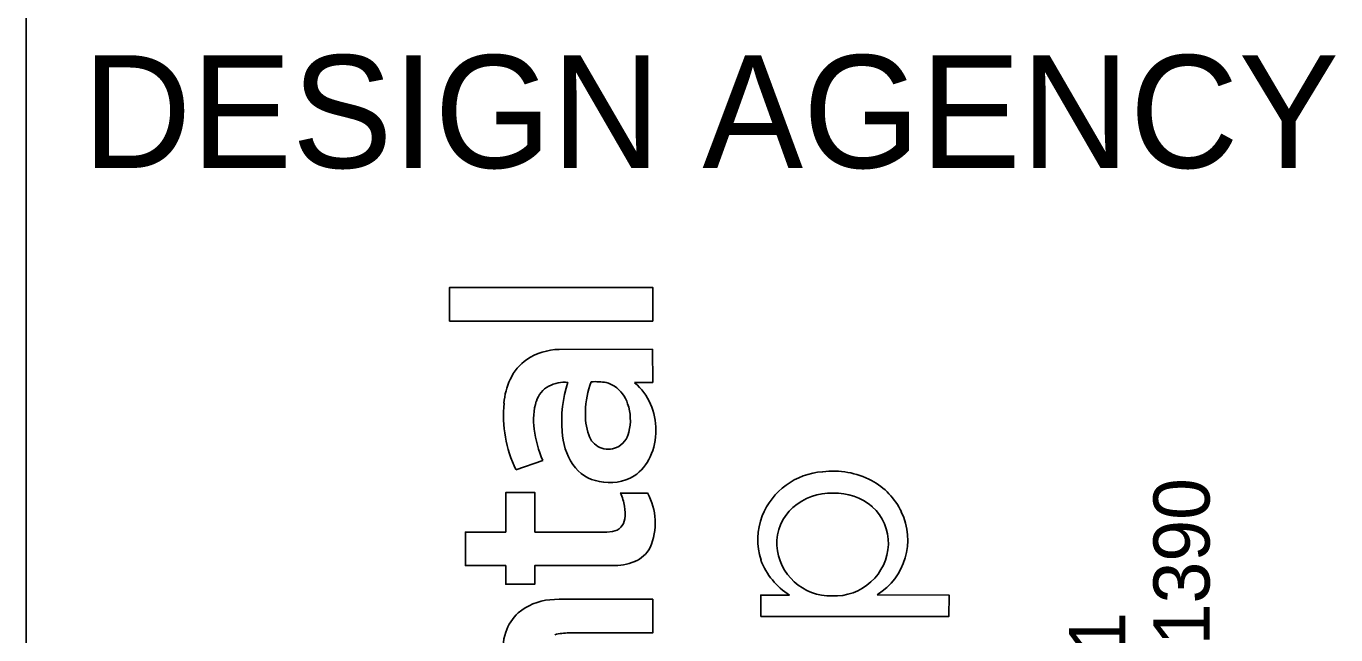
# Model space of a CAD drawing. Extents: x -0.3 to 34, y 0 to 22.
# Drawn here: x 32 to 33.162, y 3.936 to 4.476 of the extents above; entities that cross this region are included whole.
import ezdxf

# ---------------------------------------------------------------- set-up
doc = ezdxf.new("R2010")
doc.units = 0
doc.layers.add('RD_X_Misc_Items', color=7, linetype='Continuous')
doc.layers.add('SV_X_Control_Cells_Found', color=7, linetype='Continuous')

msp = doc.modelspace()

# ---------------------------------------------------------------- linework, layer by layer
at = {"layer": 'RD_X_Misc_Items'}
for p, q in [((32.3756, 4.2141), (32.3756, 4.244)), ((32.3756, 4.244), (32.5557, 4.244)), ((32.5557, 4.244), (32.5557, 4.2141)), ((32.5557, 4.2141), (32.3756, 4.2141)), ((32.4727, 4.189), (32.5555, 4.1892)), ((32.5555, 4.1892), (32.5557, 4.1596)), ((32.5557, 4.1596), (32.5397, 4.1596)), ((32.4582, 4.0904), (32.4343, 4.0823)), ((32.4254, 4.027), (32.4255, 4.0621)), ((32.4255, 4.0621), (32.4511, 4.0621)), ((32.4511, 4.0621), (32.4512, 4.027)), ((32.527, 4.0616), (32.5511, 4.0616)), ((32.3896, 3.9972), (32.3896, 4.027)), ((32.3896, 4.027), (32.4254, 4.027)), ((32.4512, 4.027), (32.515, 4.027)), ((32.515, 4.027), (32.52, 4.0275)), ((32.4254, 3.9972), (32.3896, 3.9972)), ((32.4254, 3.9807), (32.4254, 3.9972)), ((32.5197, 3.9972), (32.4511, 3.9972)), ((32.4511, 3.9972), (32.4511, 3.9807)), ((32.4511, 3.9807), (32.4254, 3.9807)), ((32.4644, 3.9669), (32.4729, 3.9673)), ((32.4729, 3.9673), (32.5557, 3.9673)), ((32.5557, 3.9673), (32.5557, 3.9375)), ((32.6515, 3.9521), (32.6515, 3.9711)), ((32.6515, 3.9711), (32.6771, 3.9711)), ((32.7549, 3.9713), (32.8186, 3.9711)), ((32.8186, 3.9711), (32.8184, 3.9521)), ((32.8184, 3.9521), (32.6515, 3.9521)), ((32.5557, 3.9375), (32.4814, 3.9375))]:
    msp.add_line(p, q, dxfattribs=at)
msp.add_lwpolyline([(32.3756, 4.2141), (32.3756, 4.244), (32.5557, 4.244), (32.5557, 4.2141)], close=True, dxfattribs=at)
for points in [[(32.4727, 4.189), (32.5555, 4.1892), (32.5557, 4.1596)], [(32.5557, 4.1596), (32.5397, 4.1596)], [(32.4582, 4.0904), (32.4343, 4.0823)], [(32.5197, 3.9972), (32.4511, 3.9972), (32.4511, 3.9807), (32.4254, 3.9807), (32.4254, 3.9972), (32.3896, 3.9972), (32.3896, 4.027), (32.4254, 4.027), (32.4255, 4.0621), (32.4511, 4.0621), (32.4512, 4.027), (32.515, 4.027), (32.52, 4.0275)], [(32.527, 4.0616), (32.5511, 4.0616)], [(32.4644, 3.9669), (32.4729, 3.9673), (32.5557, 3.9673), (32.5557, 3.9375), (32.4814, 3.9375)], [(32.7549, 3.9713), (32.8186, 3.9711), (32.8184, 3.9521), (32.6515, 3.9521)], [(32.6515, 3.9521), (32.6515, 3.9711), (32.6771, 3.9711)]]:
    msp.add_lwpolyline(points, dxfattribs=at)
for centre, radius, start, end in [((32.4745, 4.1326), 0.0565, 91.8942, 122.6317), ((32.4745, 4.1326), 0.0565, 91.8942, 122.6317), ((32.4685, 4.1447), 0.043, 124.537, 155.6594), ((32.4685, 4.1447), 0.043, 124.537, 155.6594), ((32.4882, 4.1361), 0.0646, 155.9764, 175.3149), ((32.4882, 4.1361), 0.0646, 155.9764, 175.3149), ((32.4779, 4.1278), 0.0321, 85.3802, 116.6222), ((32.4779, 4.1278), 0.0321, 85.3802, 116.6222), ((32.5879, 4.1251), 0.1129, 162.0821, 184.5285), ((32.5879, 4.1251), 0.1129, 162.0821, 184.5285), ((32.5801, 4.1313), 0.0841, 159.8366, 178.0362), ((32.5801, 4.1313), 0.0841, 159.8366, 178.0362), ((32.5051, 4.1074), 0.053, 79.6696, 94.2322), ((32.5051, 4.1074), 0.053, 79.6696, 94.2322), ((32.5089, 4.1364), 0.0238, 56.8913, 76.2149), ((32.5089, 4.1364), 0.0238, 56.8913, 76.2149), ((32.5055, 4.1191), 0.0529, 358.0746, 49.762), ((32.5055, 4.1191), 0.0529, 358.0746, 49.762), ((32.4753, 4.1356), 0.024, 119.4252, 161.6629), ((32.4753, 4.1356), 0.024, 119.4252, 161.6629), ((32.5052, 4.1318), 0.0297, 17.5984, 55.7282), ((32.5052, 4.1318), 0.0297, 17.5984, 55.7282), ((32.5364, 4.1308), 0.113, 174.6101, 205.3899), ((32.5364, 4.1308), 0.113, 174.6101, 205.3899), ((32.5076, 4.1265), 0.0576, 163.1369, 188.1675), ((32.5076, 4.1265), 0.0576, 163.1369, 188.1675), ((32.4916, 4.1264), 0.0443, 345.9408, 18.9919), ((32.4916, 4.1264), 0.0443, 345.9408, 18.9919), ((32.5466, 4.1303), 0.0506, 175.5903, 199.8857), ((32.5466, 4.1303), 0.0506, 175.5903, 199.8857), ((32.5473, 4.1297), 0.0973, 186.7598, 203.7981), ((32.5473, 4.1297), 0.0973, 186.7598, 203.7981), ((32.5328, 4.1187), 0.0575, 182.5676, 213.7144), ((32.5328, 4.1187), 0.0575, 182.5676, 213.7144), ((32.5164, 4.1189), 0.0184, 198.2844, 293.3081), ((32.5164, 4.1189), 0.0184, 198.2844, 293.3081), ((32.5152, 4.1199), 0.0199, 295.2883, 347.4639), ((32.5152, 4.1199), 0.0199, 295.2883, 347.4639), ((32.5019, 4.1168), 0.0566, 336.016, 0.5951), ((32.5019, 4.1168), 0.0566, 336.016, 0.5951), ((32.5175, 4.1097), 0.0394, 303.4436, 336.18), ((32.5175, 4.1097), 0.0394, 303.4436, 336.18), ((32.5149, 4.1078), 0.0366, 215.0668, 259.8133), ((32.5149, 4.1078), 0.0366, 215.0668, 259.8133), ((32.7108, 4.0182), 0.0624, 93.9866, 158.3119), ((32.7108, 4.0182), 0.0624, 93.9866, 158.3119), ((32.7156, 4.0065), 0.0746, 62.6889, 97.0135), ((32.7156, 4.0065), 0.0746, 62.6889, 97.0135), ((32.5175, 4.1131), 0.0423, 257.5256, 300.882), ((32.5175, 4.1131), 0.0423, 257.5256, 300.882), ((32.7212, 4.0191), 0.0608, 25.0657, 61.9602), ((32.7212, 4.0191), 0.0608, 25.0657, 61.9602), ((32.4863, 4.042), 0.0452, 10.1545, 25.723), ((32.4863, 4.042), 0.0452, 10.1545, 25.723), ((32.503, 4.0351), 0.0549, 336.589, 28.8991), ((32.503, 4.0351), 0.0549, 336.589, 28.8991), ((32.7138, 4.0102), 0.0513, 87.8965, 131.1812), ((32.7138, 4.0102), 0.0513, 87.8965, 131.1812), ((32.7175, 4.0102), 0.0513, 49.9089, 92.0363), ((32.7175, 4.0102), 0.0513, 49.9089, 92.0363), ((32.4957, 4.0436), 0.0356, 351.914, 10.2059), ((32.4957, 4.0436), 0.0356, 351.914, 10.2059), ((32.7092, 4.0167), 0.0434, 132.3289, 182.0949), ((32.7092, 4.0167), 0.0434, 132.3289, 182.0949), ((32.7215, 4.0173), 0.0433, 358.0487, 47.9447), ((32.7215, 4.0173), 0.0433, 358.0487, 47.9447), ((32.7245, 4.02), 0.0574, 301.9776, 25.6418), ((32.7245, 4.02), 0.0574, 301.9776, 25.6418), ((32.5184, 4.04), 0.0126, 277.6142, 353.7918), ((32.5184, 4.04), 0.0126, 277.6142, 353.7918), ((32.707, 4.0202), 0.0581, 158.656, 198.171), ((32.707, 4.0202), 0.0581, 158.656, 198.171), ((32.5291, 4.0261), 0.0275, 292.6889, 332.0598), ((32.5291, 4.0261), 0.0275, 292.6889, 332.0598), ((32.7135, 4.0181), 0.0478, 183.5974, 271.7045), ((32.7135, 4.0181), 0.0478, 183.5974, 271.7045), ((32.7172, 4.018), 0.0477, 267.3149, 357.4019), ((32.7172, 4.018), 0.0477, 267.3149, 357.4019), ((32.5209, 4.0486), 0.0514, 268.6727, 291.5235), ((32.5209, 4.0486), 0.0514, 268.6727, 291.5235), ((32.7103, 4.0243), 0.0627, 200.8399, 238.0162), ((32.7103, 4.0243), 0.0627, 200.8399, 238.0162), ((32.4687, 3.9172), 0.0499, 94.9706, 130.2248), ((32.4687, 3.9172), 0.0499, 94.9706, 130.2248), ((32.4635, 3.9255), 0.0402, 132.2238, 161.6823), ((32.4635, 3.9255), 0.0402, 132.2238, 161.6823), ((32.4787, 3.9211), 0.056, 162.274, 187.7917), ((32.4787, 3.9211), 0.056, 162.274, 187.7917), ((32.4811, 3.8915), 0.046, 89.6051, 105.3303), ((32.4811, 3.8915), 0.046, 89.6051, 105.3303)]:
    msp.add_arc(centre, radius, start, end, dxfattribs=at)
at = {"layer": 'SV_X_Control_Cells_Found'}
msp.add_line((32, 0.5), (32, 21.5), dxfattribs=at)

# ---------------------------------------------------------------- texts
at = {"layer": 'RD_X_Misc_Items'}
msp.add_text('DESIGN AGENCY', height=0.1, dxfattribs=at).set_placement((32.05, 4.35))
for s, p in [('800.835.1390', (33.0497, 3.6671)), ('450 GRANT ST., AKRON, OH  44311', (32.9749, 2.8374))]:
    msp.add_text(s, height=0.049846, rotation=90, dxfattribs=at).set_placement(p)

doc.saveas('drawing.dxf')
